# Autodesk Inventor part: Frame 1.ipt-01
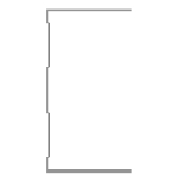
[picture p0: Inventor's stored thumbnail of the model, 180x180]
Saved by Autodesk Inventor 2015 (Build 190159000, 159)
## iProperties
_CCFamilyMember: 1
_CCFamilyDisplayName: Kévin - Kévin Novo
_FrameMemberDoc: Frame Member File
_Version: 15.0.0
_GetPNFromCC: 1
Created: 2015-04
Part Number: Frame 1.ipt-01
Material: Aluminum 6061
Description: Kévin Novo
Document SubType Name: Modeling
Standard: Kevin
Designer: suporte
Standards Organization: Kevin
Language: en-US
Size Designation: (Unnamed 1)
Categories: <MemberInstance><Categories><Category DisplayName="Structural Shapes" InternalName="089c4875-fa83-4c05-b084-43b9cc11f5ed" Mnemonic="GRDR"><CategoryParameter Dis
Density: 2.7 g/cm^3
Appearance: Aluminum - Flat
IsCustomPart: 1
G_L: 1750,000 mm
G_W: 50,000 mm
G_H: 75,000 mm
+14B16D7A-3EDF-47EE-B036-D7DA7C31691F+CUTDETAIL1: Cut
+7D595018-EB71-475E-9EFC-B886661EFD07+CUTDETAIL2: Cut
Author: suporte
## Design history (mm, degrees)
node "Start Plane"
node "End Plane"
sketch "Sketch"
  geometry: L1 (24.7, 37.5)-(24.7, 36.9); L2 (24.7, 36.9)-(-24.7, 36.9); L3 (-24.7, -36.9)-(24.7, -36.9); L4 (24.7, -36.9)-(24.7, -37.5); L5 (24.7, -37.5)-(-25.3, -37.5); L6 (-25.3, 37.5)-(24.7, 37.5); L7 (-24.7, 36.9)-(-24.7, 31.9); L8 (-24.7, 31.9)-(-23.3, 30.5); L9 (-23.3, 30.5)-(-23.3, 10.934); L10 (-23.3, 10.934)-(-24.7, 9.534); L11 (-24.7, 9.534)-(-24.7, -9.534); L12 (-24.7, -9.534)-(-23.3, -10.934); L13 (-23.3, -10.934)-(-23.3, -30.5); L14 (-23.3, -30.5)-(-24.7, -31.9); L15 (-24.7, -31.9)-(-24.7, -36.9); L16 (-25.3, -37.5)-(-25.3, -31.651); L17 (-25.3, -31.651)-(-23.9, -30.251); L18 (-23.9, -30.251)-(-23.9, -11.183); L19 (-23.9, -11.183)-(-25.3, -9.783); L20 (-25.3, -9.783)-(-25.3, 9.783); L21 (-25.3, 9.783)-(-23.9, 11.183); L22 (-23.9, 11.183)-(-23.9, 30.251); L23 (-23.9, 30.251)-(-25.3, 31.651); L24 (-25.3, 31.651)-(-25.3, 37.5); L25 (-25.3, 0)-(30.37, 0); 3 further points
  constraints: 50 end point, 10 point on line, 9 parallel, 5 perpendicular, 4 equal length, 3 midpoint, 3 vertical, 2 vertical alignment, 1 collinear, 1 horizontal, 1 horizontal alignment
  dimensions: "d3" = 0.6 distance of L1.start L1.end (= d6); "d5" = 75 distance between parallel lines of L5 L6; "d6" = 0.6 distance between parallel lines of L24 L7 (= d8); "d7" = 0.6 distance between parallel lines of L8 L23 (= d8); "d8" = 0.6 distance between parallel lines of L22 L9 (= d12); "Espessura" = 0.6 distance between parallel lines of L17 L14; "d10" = 0.6 distance between parallel lines of L13 L18 (= Espessura); "d11" = 0.6 distance between parallel lines of L12 L19 (= Espessura); "d12" = 0.6 distance between parallel lines of L21 L10 (= d11); "d13" = 5 distance of L2.end L7.end; "d15" = 135 deg angle of L9 L8; "d16" = 2 distance between parallel lines of L24 L9; "d17" = 50 distance of L6.start L1.start
extrude "Body" join sketch "Sketch" stored distance "d24" = 0.13; taper "d25" = 0 deg
node "Driven Length"
  sketch "Sketch10"
    geometry: L1 (0, 0)-(10, 0) reference
    constraints: 2 end point, 1 horizontal
  workplane "Work Plane7"
  sketch "Sketch11"
    geometry: L1 (-2, 25)-(12, 25) reference; L2 (-2, 1775)-(12, 1775) reference
    dimensions: "d27" = 1750 distance between parallel lines of L1 L2 (derived)
workplane "Work Plane8"
split "Split1"
workplane "Work Plane9"
split "Split2"
body "Solid1"
other parameters: "G_OFFSET_START" = -25 [user parameter; used in 1 equation term], "G_OFFSET_END" = -25 [user parameter; used in 1 equation term], "d22" = 25 (= -G_OFFSET_START), "d23" = 1775 (= tamanho + G_OFFSET_END), "G_L" = 1750 (= d27) [user parameter], "d34" = 90 deg
